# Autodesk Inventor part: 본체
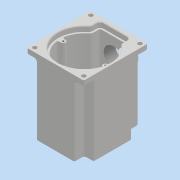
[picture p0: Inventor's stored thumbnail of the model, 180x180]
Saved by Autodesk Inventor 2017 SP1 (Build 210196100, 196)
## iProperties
Part Number: 본체
Material: 일반
Document SubType Name: Modeling
Designer: MRC
Density: 1 g/cm^3
Appearance: 기본값
Author: MRC
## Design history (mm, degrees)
sketch "스케치1"
  geometry: L1 (-49, -50)-(49, -50); L2 (49, -50)-(49, 60); L3 (49, 60)-(-49, 60); L4 (-49, 60)-(-49, -50); L5 (-49, -50)-(49, 60); L6 (49, -50)-(-49, 60); 3 further points
  constraints: 12 end point, 3 midpoint, 2 parallel, 1 horizontal, 1 perpendicular, 1 vertical alignment
  dimensions: "d0" = 98 distance of L2.end L3.end; "d1" = 110 distance of L3.end L1.start; "d2" = 50 distance from line of point (0, 0) L1
extrude "돌출1" new body sketch "스케치1" distance "d3" = 130; taper "d4" = 0 deg
sketch "스케치2"
  geometry: L1 (-26, 53)-(26, 53); L2 (26, 53)-(26, 28); L3 (26, 28)-(-26, 28); L4 (-26, 28)-(-26, 53); L5 (-26, 53)-(26, 28); L6 (26, 53)-(-26, 28); C1 r 45 at (0, 0); 3 further points
  constraints: 12 end point, 3 midpoint, 2 parallel, 1 centre point, 1 coincident, 1 horizontal, 1 perpendicular, 1 vertical alignment
  dimensions: "d5" = 52 distance of L1.start L1.end; "d6" = 90 diameter of C1; "d7" = 53 distance from line of L1 point (0, 0); "d8" = 25 distance of L3.end L1.start
extrude "돌출2" cut sketch "스케치2" distance "d9" = 9; taper "d10" = 0 deg
sketch "스케치3"
  geometry: L1 (26, 53)-(26, 36.729) reference; L2 (-26, 53)-(26, 53) reference; L3 (-26, 36.729)-(-26, 53) reference; L4 (26, 36.729)-(26, 53) reference; L5 (26, 53)-(-26, 53) reference; L6 (-26, 53)-(-26, 36.729) reference; L7 (49, 60)-(49, -50) reference; L8 (49, -50)-(-49, -50) reference; L9 (-49, -50)-(-49, 60) reference; L10 (-49, 60)-(49, 60) reference; L11 (-23, 50)-(23, 50); L12 (-23, 35.143)-(-23, 50); L13 (23, 50)-(23, 35.143); L14 (-36, 4)-(-41.809, 4); L15 (-36, -4)-(-41.809, -4); A1 r 45 centre (0, 0) between (-26, 36.729) and (26, 36.729) reference; A2 r 45 centre (0, 0) between (-26, 36.729) and (26, 36.729) reference; A3 r 42 centre (0, 0) between (-23, 35.143) and (23, 35.143); A4 r 4 centre (-36, 0) between (-36, -4) and (-36, 4)
  constraints: 10 end point, 6 point on circle, 4 parallel, 2 centre point, 2 horizontal, 2 tangent, 1 horizontal alignment
  dimensions: "d11" = 3 distance between parallel lines of L2 L11; "d12" = 3 distance between parallel lines of L3 L12; "d14" = 3 radial gap between concentric circles of A1 A3; "d15" = 3 distance between parallel lines of L1 L13; "d16" = 8 diameter of A4; "d18" = 36 distance of A4.centre A1.centre
  node "절단 모서리 투영1"
extrude "돌출3" cut sketch "스케치3" distance "d20" = 112; taper "d21" = 0 deg
extrude "돌출4" join sketch "스케치3" stored distance "d22" = 112; taper "d23" = 0 deg
sketch "스케치4"
  geometry: A1 r 42 centre (0, 0) between (41.809, 4) and (23, 35.143) reference; A2 r 42 centre (0, 0) between (-23, 35.143) and (-41.809, 4) reference; A3 r 21 centre (0, 11) between (8.978, -7.984) and (-8.978, -7.984); A4 r 15 centre (0, -20) between (-8.978, -7.984) and (8.978, -7.984)
  constraints: 4 point on circle, 2 centre point, 2 vertical alignment
  dimensions: "d27" = 42 diameter of A3; "d28" = 30 diameter of A4; "d29" = 11 distance of A3.centre A2.centre; "d30" = 20 distance of A1.centre A4.centre
extrude "돌출5" join sketch "스케치4" distance "d31" = 7; taper "d32" = 0 deg
hole "구멍1" diameter "d35" = 19; stored, may be unused: countersink angle "d39" = 90 deg, drill point angle "d41" = 0 deg; dims "d33" = 10, "d34" = 10, "d36" = 6, "d37" = 22, "d38" = 7, "d40" = 10
hole "구멍2" diameter "d44" = 28; stored, may be unused: countersink angle "d48" = 90 deg, drill point angle "d50" = 0 deg; dims "d42" = 10, "d43" = 10, "d45" = 6, "d46" = 35, "d47" = 10, "d49" = 10
sketch "스케치5"
  geometry: C1 r 14 at (0, 11) reference; C2 r 27 at (0, 11); 1 further point
  constraints: 1 centre point, 1 coincident
  dimensions: "d51" = 54 diameter of C2
extrude "돌출6" join sketch "스케치5" distance "d52" = 7; taper "d53" = 0 deg
sketch "스케치6"
  geometry: C1 r 14 at (0, 0) reference; C2 r 27 at (0, 0) reference; C3 r 16 at (0, 0); 1 further point
  constraints: 1 centre point, 1 coincident
  dimensions: "d54" = 32 diameter of C3
extrude "돌출7" cut sketch "스케치6" distance "d55" = 8.3; taper "d56" = 0 deg
sketch "스케치7"
  geometry: L1 (98, 0)-(0, 0) reference; C1 r 22.5 at (49, 40); 2 further points
  constraints: 1 centre point, 1 midpoint, 1 vertical alignment
  dimensions: "d57" = 45 diameter of C1; "d58" = 40 distance of point (49, 0) C1.centre
extrude "돌출8" join sketch "스케치7" distance "d59" = 10; taper "d60" = 0 deg
sketch "스케치8"
  geometry: L1 (98, 0)-(0, 0) reference; C1 r 22.5 at (49, 40) reference; C2 r 15 at (49, 89); 2 further points
  constraints: 1 centre point, 1 midpoint, 1 vertical alignment
  dimensions: "d61" = 30 diameter of C2; "d62" = 49 distance of C2.centre C1.centre
extrude "돌출9" join sketch "스케치8" distance "d63" = 5; taper "d64" = 0 deg
hole "구멍3" diameter "d67" = 20; stored, may be unused: countersink angle "d71" = 90 deg, drill point angle "d73" = 0 deg; dims "d65" = 10, "d66" = 10, "d68" = 6, "d69" = 35, "d70" = 10, "d72" = 10
sketch "스케치9"
  geometry: C1 r 10 at (23, -80) reference; C2 r 15 at (23, -80); 1 further point
  constraints: 1 centre point, 1 coincident
  dimensions: "d74" = 30 diameter of C2
extrude "돌출10" cut sketch "스케치9" distance "d75" = 5; taper "d76" = 0 deg
hole "구멍4" diameter "d79" = 33.376; stored, may be unused: countersink angle "d83" = 90 deg, drill point angle "d85" = 0 deg; dims "d77" = 10, "d78" = 10, "d80" = 40, "d81" = 35, "d82" = 10, "d84" = 77.3
hole "구멍5" diameter "d88" = 3.242; stored, may be unused: countersink angle "d92" = 90 deg, drill point angle "d94" = 118 deg; dims "d86" = 10, "d87" = 10, "d89" = 7, "d90" = 35, "d91" = 10, "d93" = 9
sketch "스케치10"
  geometry: L1 (49, 60)-(33, 60); L2 (33, 60)-(33, 33); L3 (33, 33)-(49, 33); L4 (49, 33)-(49, 60); L5 (-49, 60)-(-33, 60); L6 (-33, 60)-(-33, 33); L7 (-33, 33)-(-49, 33); L8 (-49, 33)-(-49, 60); 1 further point
  constraints: 16 end point, 4 parallel, 2 equal length, 2 horizontal, 2 perpendicular
  dimensions: "d98" = 27 distance of L1.end L2.end; "d99" = 16 distance of L6.end L7.end
extrude "돌출11" cut sketch "스케치10" distance "d100" = 120; taper "d101" = 0 deg
sketch "스케치11"
  geometry: L1 (49, -50)-(33, -50); L2 (33, -50)-(33, -33); L3 (33, -33)-(49, -33); L4 (49, -33)-(49, -50); L5 (-49, -50)-(-33, -50); L6 (-33, -50)-(-33, -33); L7 (-33, -33)-(-49, -33); L8 (-49, -33)-(-49, -50); 1 further point
  constraints: 16 end point, 4 parallel, 2 equal length, 2 horizontal, 2 perpendicular
  dimensions: "d102" = 16 distance of L2.end L3.end; "d103" = 17 distance of L1.end L2.end
extrude "돌출12" cut sketch "스케치11" distance "d104" = 120; taper "d105" = 0 deg
sketch "스케치12"
  geometry: L1 (-49, 60)-(-33, 60) reference; C1 r 3.5 at (-42, 53); C2 r 3.5 at (42, 53); C3 r 3.5 at (42, -43); C4 r 3.5 at (-42, -43); 1 further point
  constraints: 4 centre point, 3 equal radius, 2 horizontal alignment, 2 vertical alignment
  dimensions: "d106" = 7 diameter of C1; "d107" = 84 distance of C2.centre C1.centre; "d108" = 96 distance of C1.centre C4.centre; "d109" = 42 horizontal distance of point (0, 0) C1.centre; "d111" = 7 distance from line of L1 C1.centre
extrude "돌출13" cut sketch "스케치12" stored distance "d112" = 120; taper "d113" = 0 deg
sketch "스케치13"
  geometry: L1 (-27, -27)-(27, -27); L2 (27, -27)-(27, 27); L3 (27, 27)-(-27, 27); L4 (-27, 27)-(-27, -27); L5 (-27, -27)-(27, 27); L6 (27, -27)-(-27, 27); C1 r 16 at (0, 0) reference; C2 r 27 at (0, 0) reference; C3 r 16 at (0, 0) reference; C4 r 27 at (0, 0) reference; C5 r 16 at (0, 0) reference; C6 r 27 at (0, 0) reference; 1 further point
  constraints: 12 end point, 2 midpoint, 2 parallel, 1 horizontal, 1 perpendicular
  dimensions: "d114" = 54 distance of L2.end L3.end; "d115" = 54 distance of L3.end L1.start
extrude "돌출14" join sketch "스케치13" stored distance "d116" = 120; taper "d117" = 0 deg
chamfer "모따기1" distance "d118" = 0.8; stored, may be unused: second distance "d119" = 2, angle "d120" = 30 deg
fillet "모깎기1" dims "d121" = 0.3
fillet "모깎기2" dims "d125" = 0.3
fillet "모깎기3" dims "d126" = 3
fillet "모깎기8" dims "d138" = 6
fillet "모깎기4" dims "d127" = 3
fillet "모깎기5" dims "d128" = 3
fillet "모깎기6" dims "d129" = 3
fillet "모깎기7" dims "d130" = 6
chamfer "모따기2" distance "d122" = 1; stored, may be unused: second distance "d123" = 2, angle "d124" = 30 deg
node "작업 평면2"
sketch "스케치16"
  geometry: L1 (-130, 104)-(-130, 83) reference; L2 (-13, 80)-(-127, 80) reference; 2 further points
  constraints: 1 other
  dimensions: "d134" = 65 distance from line of L1 point (-65, 47); "d135" = 33 distance from line of L2 point (-65, 47)
feature "엠보싱1" sketch "스케치16" dims "d136" = 0.5, "d137" = 0
node "솔리드1"
pattern_circular "원형 패턴1" dims angle "d25" = 360 deg
pattern_circular "원형 패턴2" dims angle "d96" = 360 deg
node "절단 모서리 투영2"
node "절단 모서리 투영3"
other parameters: "d133" = 140.5
